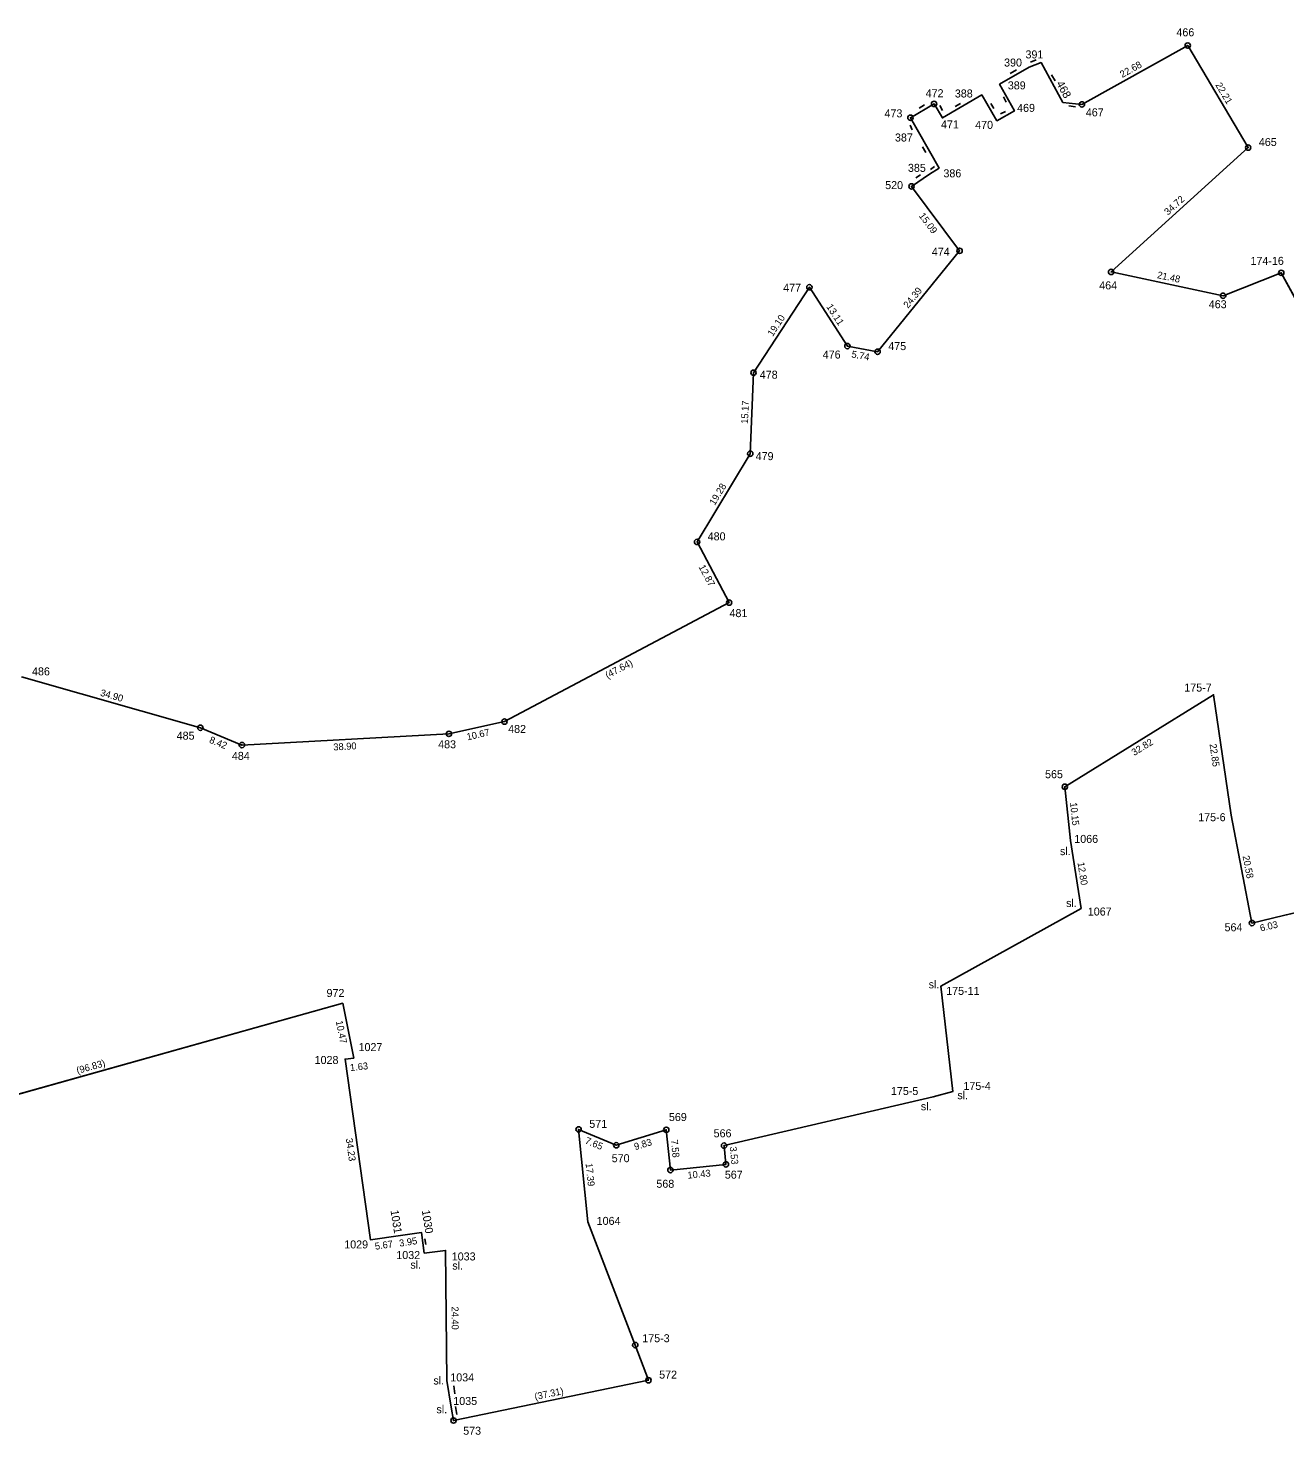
# Model space of a CAD drawing. Extents: x -555170 to -550532, y -1039598 to -1034701.
# Drawn here: x -554262.1 to -554026.5, y -1037853.4 to -1037589.8 of the extents above; entities that cross this region are included whole.
import ezdxf

# ---------------------------------------------------------------- set-up
doc = ezdxf.new("R2010")
doc.units = 0
for name, color, linetype in [('Vrstva 10', 7, 'Continuous'), ('Vrstva 40', 7, 'Continuous'), ('Vrstva 43', 7, 'Continuous'), ('Vrstva 48', 7, 'Continuous')]:
    doc.layers.add(name, color=color, linetype=linetype)

msp = doc.modelspace()

# ---------------------------------------------------------------- linework, layer by layer
at = {"layer": 'Vrstva 10'}
for p, q in [((-554073.13, -1037595.73), (-554074.17, -1037596.11)), ((-554076.83, -1037597.6), (-554077.99, -1037598.24)), ((-554070.26, -1037598.54), (-554069.58, -1037599.63)), ((-554079.26, -1037602.63), (-554078.76, -1037603.64)), ((-554094.09, -1037604.15), (-554095.08, -1037604.76)), ((-554091.18, -1037604.28), (-554090.67, -1037605.19)), ((-554087.3, -1037603.87), (-554088.34, -1037604.48)), ((-554081.62, -1037603.87), (-554081.09, -1037604.84)), ((-554078.91, -1037605.39), (-554079.8, -1037605.85)), ((-554065.78, -1037604.53), (-554066.99, -1037604.35)), ((-554096.78, -1037607.94), (-554096.35, -1037608.82)), ((-554094.45, -1037612.02), (-554093.84, -1037613.06)), ((-554092.22, -1037615.67), (-554092.95, -1037616.23)), ((-554094.83, -1037617.27), (-554095.72, -1037617.85)), ((-554187.7, -1037816.67), (-554187.55, -1037817.74)), ((-554182.31, -1037844.21), (-554182.1, -1037845.71)), ((-554181.94, -1037848.1), (-554181.69, -1037849.59))]:
    msp.add_line(p, q, dxfattribs=at)
at = {"layer": 'Vrstva 40'}
for p, q in [((-554044.74, -1037593.02), (-554064.56, -1037604.06)), ((-554033.4, -1037612.15), (-554044.74, -1037593.02)), ((-554074.45, -1037597.07), (-554080.01, -1037600.29)), ((-554072.22, -1037596.22), (-554074.45, -1037597.07)), ((-554068.14, -1037603.67), (-554072.22, -1037596.22)), ((-554080.01, -1037600.29), (-554077.21, -1037605.29)), ((-554083.34, -1037602.28), (-554090.72, -1037606.6)), ((-554080.48, -1037607.11), (-554083.34, -1037602.28)), ((-554064.56, -1037604.06), (-554068.14, -1037603.67)), ((-554092.27, -1037603.96), (-554096.7, -1037606.56)), ((-554090.72, -1037606.6), (-554092.27, -1037603.96)), ((-554077.21, -1037605.29), (-554080.48, -1037607.11)), ((-554096.7, -1037606.56), (-554095.19, -1037609.22)), ((-554095.19, -1037609.22), (-554091.35, -1037615.99)), ((-554059.09, -1037635.45), (-554033.4, -1037612.15)), ((-554091.35, -1037615.99), (-554093.16, -1037617.16)), ((-554093.16, -1037617.16), (-554096.5, -1037619.43)), ((-554096.5, -1037619.43), (-554087.48, -1037631.5)), ((-554087.48, -1037631.5), (-554102.86, -1037650.41)), ((-554038.11, -1037639.91), (-554059.09, -1037635.45)), ((-554027.21, -1037635.62), (-554038.11, -1037639.91)), ((-554013.33, -1037660.96), (-554027.21, -1037635.62)), ((-554115.65, -1037638.34), (-554126.11, -1037654.35)), ((-554108.53, -1037649.35), (-554115.65, -1037638.34)), ((-554102.86, -1037650.41), (-554108.53, -1037649.35)), ((-554126.11, -1037654.35), (-554126.72, -1037669.52)), ((-554126.72, -1037669.52), (-554136.7, -1037686.06)), ((-554136.7, -1037686.06), (-554130.68, -1037697.43)), ((-554130.68, -1037697.43), (-554172.78, -1037719.73)), ((-554229.79, -1037720.89), (-554263.34, -1037711.37)), ((-554067.76, -1037731.95), (-554039.89, -1037714.69)), ((-554039.89, -1037714.69), (-554036.61, -1037737.29)), ((-554221.99, -1037724.12), (-554229.79, -1037720.89)), ((-554183.2, -1037722.03), (-554221.99, -1037724.12)), ((-554172.78, -1037719.73), (-554183.2, -1037722.03)), ((-554066.7, -1037742.04), (-554067.76, -1037731.95)), ((-554036.61, -1037737.29), (-554032.69, -1037757.49)), ((-554064.72, -1037754.73), (-554066.7, -1037742.04)), ((-554026.81, -1037756.1), (-554004.57, -1037750.84)), ((-554090.99, -1037769.3), (-554064.72, -1037754.73)), ((-554032.69, -1037757.49), (-554026.81, -1037756.1)), ((-554088.77, -1037789.06), (-554090.99, -1037769.3)), ((-554296.34, -1037798.66), (-554203.1, -1037772.53)), ((-554203.1, -1037772.53), (-554201.05, -1037782.8)), ((-554201.05, -1037782.8), (-554202.66, -1037782.97)), ((-554202.66, -1037782.97), (-554197.89, -1037816.89)), ((-554131.64, -1037799.21), (-554092.45, -1037790.08)), ((-554092.45, -1037790.08), (-554088.77, -1037789.06)), ((-554157.14, -1037813.46), (-554158.89, -1037796.17)), ((-554158.89, -1037796.17), (-554151.83, -1037799.13)), ((-554151.83, -1037799.13), (-554142.46, -1037796.24)), ((-554142.46, -1037796.24), (-554141.69, -1037803.78)), ((-554131.28, -1037802.72), (-554131.64, -1037799.21)), ((-554141.69, -1037803.78), (-554131.28, -1037802.72)), ((-554148.27, -1037836.57), (-554157.14, -1037813.46)), ((-554197.89, -1037816.89), (-554192.28, -1037816.06)), ((-554188.36, -1037815.47), (-554192.28, -1037816.06)), ((-554188.36, -1037815.47), (-554187.83, -1037819.35)), ((-554187.83, -1037819.35), (-554183.83, -1037818.84)), ((-554183.83, -1037818.84), (-554183.61, -1037843.21)), ((-554145.8, -1037843.17), (-554148.27, -1037836.57)), ((-554183.61, -1037843.21), (-554182.77, -1037848.25)), ((-554182.34, -1037850.72), (-554145.8, -1037843.17)), ((-554182.77, -1037848.25), (-554182.34, -1037850.72))]:
    msp.add_line(p, q, dxfattribs=at)
at = {"layer": 'Vrstva 43'}
for p, q in [((-554044.74, -1037593.02), (-554044.74, -1037593.02)), ((-554074.45, -1037597.07), (-554074.45, -1037597.07)), ((-554072.22, -1037596.22), (-554072.22, -1037596.22)), ((-554080.01, -1037600.29), (-554080.01, -1037600.29)), ((-554083.34, -1037602.28), (-554083.34, -1037602.28)), ((-554068.14, -1037603.67), (-554068.14, -1037603.67)), ((-554092.27, -1037603.96), (-554092.27, -1037603.96)), ((-554077.21, -1037605.29), (-554077.21, -1037605.29)), ((-554064.56, -1037604.06), (-554064.56, -1037604.06)), ((-554096.7, -1037606.56), (-554096.7, -1037606.56)), ((-554090.72, -1037606.6), (-554090.72, -1037606.6)), ((-554080.48, -1037607.11), (-554080.48, -1037607.11)), ((-554095.19, -1037609.22), (-554095.19, -1037609.22)), ((-554033.4, -1037612.15), (-554033.4, -1037612.15)), ((-554091.35, -1037615.99), (-554091.35, -1037615.99)), ((-554096.5, -1037619.43), (-554096.5, -1037619.43)), ((-554093.16, -1037617.16), (-554093.16, -1037617.16)), ((-554087.48, -1037631.5), (-554087.48, -1037631.5)), ((-554059.09, -1037635.45), (-554059.09, -1037635.45)), ((-554027.21, -1037635.62), (-554027.21, -1037635.62)), ((-554115.65, -1037638.34), (-554115.65, -1037638.34)), ((-554038.11, -1037639.91), (-554038.11, -1037639.91)), ((-554108.53, -1037649.35), (-554108.53, -1037649.35)), ((-554102.86, -1037650.41), (-554102.86, -1037650.41)), ((-554126.11, -1037654.35), (-554126.11, -1037654.35)), ((-554126.72, -1037669.52), (-554126.72, -1037669.52)), ((-554136.7, -1037686.06), (-554136.7, -1037686.06)), ((-554130.68, -1037697.43), (-554130.68, -1037697.43)), ((-554039.89, -1037714.69), (-554039.89, -1037714.69)), ((-554229.79, -1037720.89), (-554229.79, -1037720.89)), ((-554183.2, -1037722.03), (-554183.2, -1037722.03)), ((-554172.78, -1037719.73), (-554172.78, -1037719.73)), ((-554221.99, -1037724.12), (-554221.99, -1037724.12)), ((-554067.76, -1037731.95), (-554067.76, -1037731.95)), ((-554036.61, -1037737.29), (-554036.61, -1037737.29)), ((-554066.7, -1037742.04), (-554066.7, -1037742.04)), ((-554064.72, -1037754.73), (-554064.72, -1037754.73)), ((-554026.81, -1037756.1), (-554026.81, -1037756.1)), ((-554032.69, -1037757.49), (-554032.69, -1037757.49)), ((-554090.99, -1037769.3), (-554090.99, -1037769.3)), ((-554203.1, -1037772.53), (-554203.1, -1037772.53)), ((-554202.66, -1037782.97), (-554202.66, -1037782.97)), ((-554201.05, -1037782.8), (-554201.05, -1037782.8)), ((-554092.45, -1037790.08), (-554092.45, -1037790.08)), ((-554088.77, -1037789.06), (-554088.77, -1037789.06)), ((-554158.89, -1037796.17), (-554158.89, -1037796.17)), ((-554142.46, -1037796.24), (-554142.46, -1037796.24)), ((-554151.83, -1037799.13), (-554151.83, -1037799.13)), ((-554131.64, -1037799.21), (-554131.64, -1037799.21)), ((-554141.69, -1037803.78), (-554141.69, -1037803.78)), ((-554131.28, -1037802.72), (-554131.28, -1037802.72)), ((-554157.14, -1037813.46), (-554157.14, -1037813.46)), ((-554197.89, -1037816.89), (-554197.89, -1037816.89)), ((-554192.28, -1037816.06), (-554192.28, -1037816.06)), ((-554188.36, -1037815.47), (-554188.36, -1037815.47)), ((-554187.83, -1037819.35), (-554187.83, -1037819.35)), ((-554183.83, -1037818.84), (-554183.83, -1037818.84)), ((-554148.27, -1037836.57), (-554148.27, -1037836.57)), ((-554183.61, -1037843.21), (-554183.61, -1037843.21)), ((-554145.8, -1037843.17), (-554145.8, -1037843.17)), ((-554182.77, -1037848.25), (-554182.77, -1037848.25)), ((-554182.34, -1037850.72), (-554182.34, -1037850.72))]:
    msp.add_line(p, q, dxfattribs=at)
for centre, radius in [((-554044.74, -1037593.02), 0.5), ((-554044.74, -1037593.02), 0.01), ((-554092.27, -1037603.96), 0.5), ((-554064.56, -1037604.06), 0.5), ((-554096.7, -1037606.56), 0.5), ((-554092.27, -1037603.96), 0.01), ((-554064.56, -1037604.06), 0.01), ((-554096.7, -1037606.56), 0.01), ((-554033.4, -1037612.15), 0.5), ((-554033.4, -1037612.15), 0.01), ((-554096.5, -1037619.43), 0.5), ((-554096.5, -1037619.43), 0.01), ((-554087.48, -1037631.5), 0.5), ((-554087.48, -1037631.5), 0.01), ((-554059.09, -1037635.45), 0.5), ((-554027.21, -1037635.62), 0.5), ((-554115.65, -1037638.34), 0.5), ((-554059.09, -1037635.45), 0.01), ((-554027.21, -1037635.62), 0.01), ((-554115.65, -1037638.34), 0.01), ((-554038.11, -1037639.91), 0.5), ((-554038.11, -1037639.91), 0.01), ((-554108.53, -1037649.35), 0.5), ((-554108.53, -1037649.35), 0.01), ((-554102.86, -1037650.41), 0.5), ((-554102.86, -1037650.41), 0.01), ((-554126.11, -1037654.35), 0.5), ((-554126.11, -1037654.35), 0.01), ((-554126.73, -1037669.52), 0.5), ((-554126.73, -1037669.52), 0.01), ((-554136.7, -1037686.06), 0.5), ((-554136.7, -1037686.06), 0.01), ((-554130.68, -1037697.43), 0.5), ((-554130.68, -1037697.43), 0.01), ((-554172.78, -1037719.73), 0.5), ((-554229.79, -1037720.89), 0.5), ((-554229.79, -1037720.89), 0.01), ((-554183.2, -1037722.03), 0.5), ((-554183.2, -1037722.03), 0.01), ((-554172.78, -1037719.73), 0.01), ((-554221.99, -1037724.12), 0.5), ((-554221.99, -1037724.12), 0.01), ((-554067.76, -1037731.95), 0.5), ((-554067.76, -1037731.95), 0.01), ((-554032.69, -1037757.49), 0.5), ((-554032.69, -1037757.49), 0.01), ((-554158.89, -1037796.17), 0.5), ((-554158.89, -1037796.17), 0.01), ((-554142.46, -1037796.24), 0.5), ((-554151.83, -1037799.13), 0.5), ((-554142.46, -1037796.24), 0.01), ((-554131.64, -1037799.21), 0.5), ((-554151.83, -1037799.13), 0.01), ((-554131.64, -1037799.21), 0.01), ((-554141.69, -1037803.78), 0.5), ((-554141.69, -1037803.78), 0.01), ((-554131.28, -1037802.72), 0.5), ((-554131.28, -1037802.72), 0.01), ((-554148.27, -1037836.57), 0.5), ((-554148.27, -1037836.57), 0.01), ((-554145.8, -1037843.17), 0.5), ((-554145.8, -1037843.17), 0.01), ((-554182.34, -1037850.72), 0.5), ((-554182.34, -1037850.72), 0.01)]:
    msp.add_circle(centre, radius, dxfattribs=at)
at = {"layer": 'Vrstva 48'}
for points in [[(-554263.34, -1037711.37), (-554229.79, -1037720.89), (-554221.99, -1037724.12), (-554183.2, -1037722.03), (-554172.78, -1037719.73), (-554130.68, -1037697.43), (-554136.7, -1037686.06), (-554126.72, -1037669.52), (-554126.11, -1037654.35), (-554115.65, -1037638.34), (-554108.53, -1037649.35), (-554102.86, -1037650.41), (-554087.48, -1037631.5), (-554096.5, -1037619.43), (-554093.16, -1037617.16), (-554091.35, -1037615.99), (-554095.19, -1037609.22), (-554096.7, -1037606.56), (-554092.27, -1037603.96), (-554090.72, -1037606.6), (-554083.34, -1037602.28), (-554080.48, -1037607.11), (-554077.21, -1037605.29), (-554080.01, -1037600.29), (-554074.45, -1037597.07), (-554072.22, -1037596.22), (-554068.14, -1037603.67), (-554064.56, -1037604.06), (-554044.74, -1037593.02), (-554033.4, -1037612.15), (-554059.09, -1037635.45), (-554038.11, -1037639.91), (-554027.21, -1037635.62), (-554013.33, -1037660.96)], [(-554004.57, -1037750.84), (-554026.81, -1037756.1), (-554032.69, -1037757.49), (-554036.61, -1037737.29), (-554039.89, -1037714.69), (-554067.76, -1037731.95), (-554066.7, -1037742.04), (-554064.72, -1037754.73), (-554090.99, -1037769.3), (-554088.77, -1037789.06), (-554092.45, -1037790.08), (-554131.64, -1037799.21), (-554131.28, -1037802.72), (-554141.69, -1037803.78), (-554142.46, -1037796.24), (-554151.83, -1037799.13), (-554158.89, -1037796.17), (-554157.14, -1037813.46), (-554148.27, -1037836.57), (-554145.8, -1037843.17), (-554182.34, -1037850.72), (-554182.77, -1037848.25), (-554183.61, -1037843.21), (-554183.83, -1037818.84), (-554187.83, -1037819.35), (-554188.36, -1037815.47), (-554192.28, -1037816.06), (-554197.89, -1037816.89), (-554202.66, -1037782.97), (-554201.05, -1037782.8), (-554203.1, -1037772.53), (-554296.34, -1037798.66)]]:
    msp.add_lwpolyline(points, dxfattribs=at)

# ---------------------------------------------------------------- texts
at = {"layer": 'Vrstva 10'}
for s, rotation, p in [('22.68', 29.135, (-554057, -1037599.11)), ('22.21', 300.679, (-554039.6, -1037600.41)), ('34.72', 42.2103, (-554048.43, -1037624.91)), ('15.09', 306.7591, (-554095.19, -1037624.95)), ('21.48', 347.9952, (-554050.55, -1037636.6)), ('24.39', 50.8857, (-554097.15, -1037642.36)), ('13.11', 302.867, (-554112.52, -1037641.97)), ('19.10', 56.8307, (-554122.51, -1037647.65)), ('5.74', 349.4545, (-554107.83, -1037651.46)), ('15.17', 87.6785, (-554127.15, -1037663.94)), ('19.28', 58.894, (-554133.38, -1037679.3)), ('12.87', 297.8923, (-554136.44, -1037690.73)), ('(47.64)', 27.9037, (-554153.49, -1037711.72)), ('34.90', 344.1534, (-554248.65, -1037714.87)), ('10.67', 12.4768, (-554179.72, -1037723.26)), ('8.42', 337.5442, (-554228.24, -1037723.64)), ('38.90', 3.0777, (-554204.83, -1037725.15)), ('32.82', 31.7747, (-554054.77, -1037726.2)), ('22.85', 278.2578, (-554040.65, -1037723.96)), ('10.15', 275.9691, (-554066.79, -1037734.94)), ('20.58', 280.9958, (-554034.46, -1037744.96)), ('12.80', 278.8683, (-554065.4, -1037746.17)), ('6.03', 13.3066, (-554031.03, -1037759.1)), ('10.47', 281.2885, (-554204.41, -1037775.9)), ('(96.83)', 15.6541, (-554252.8, -1037785.78)), ('1.63', 6.0275, (-554201.67, -1037785.23)), ('34.23', 278.0047, (-554202.53, -1037797.89)), ('7.65', 337.2356, (-554157.8, -1037798.74)), ('9.83', 17.1112, (-554148.27, -1037800.07)), ('7.58', 275.8273, (-554141.61, -1037798.14)), ('3.53', 275.8273, (-554130.58, -1037799.43)), ('17.39', 275.7631, (-554157.59, -1037802.55)), ('10.43', 5.8273, (-554138.43, -1037805.41)), ('5.67', 8.4159, (-554196.98, -1037818.73)), ('3.95', 8.5594, (-554192.42, -1037818.15)), ('24.40', 270.5172, (-554182.71, -1037829.36)), ('(37.31)', 11.6723, (-554167.01, -1037846.89))]:
    msp.add_text(s, height=1.3, rotation=rotation, dxfattribs=at).set_placement(p)
at = {"layer": 'Vrstva 43'}
for s, p in [('466', (-554046.85, -1037591.29)), ('390', (-554079.15, -1037596.96)), ('391', (-554075.14, -1037595.44)), ('389', (-554078.45, -1037601.24)), ('472', (-554093.85, -1037602.71)), ('388', (-554088.38, -1037602.76)), ('473', (-554101.56, -1037606.48)), ('469', (-554076.71, -1037605.46)), ('467', (-554063.83, -1037606.29)), ('471', (-554090.98, -1037608.56)), ('470', (-554084.57, -1037608.64)), ('387', (-554099.6, -1037611.01)), ('465', (-554031.4, -1037611.85)), ('385', (-554097.17, -1037616.7)), ('386', (-554090.52, -1037617.72)), ('520', (-554101.44, -1037619.93)), ('474', (-554092.69, -1037632.41)), ('174-16', (-554032.97, -1037634.13)), ('477', (-554120.55, -1037639.16)), ('464', (-554061.32, -1037638.73)), ('463', (-554040.79, -1037642.26)), ('476', (-554113.14, -1037651.69)), ('475', (-554100.86, -1037650.11)), ('478', (-554124.94, -1037655.46)), ('479', (-554125.71, -1037670.73)), ('480', (-554134.7, -1037685.76)), ('481', (-554130.61, -1037700.15)), ('486', (-554261.34, -1037711.07)), ('175-7', (-554045.37, -1037714.11)), ('485', (-554234.23, -1037723.12)), ('482', (-554172.1, -1037721.86)), ('483', (-554185.22, -1037724.73)), ('484', (-554223.88, -1037726.91)), ('565', (-554071.47, -1037730.34)), ('175-6', (-554042.77, -1037738.4)), ('sl.', (-554068.68, -1037744.76)), ('1066', (-554065.99, -1037742.47)), ('sl.', (-554067.53, -1037754.49)), ('1067', (-554063.46, -1037756.08)), ('564', (-554037.83, -1037759.03)), ('sl.', (-554093.29, -1037769.73)), ('175-11', (-554090, -1037770.95)), ('972', (-554206.14, -1037771.35)), ('1027', (-554200.14, -1037781.48)), ('1028', (-554208.37, -1037783.9)), ('175-5', (-554100.36, -1037789.72)), ('175-4', (-554086.77, -1037788.76)), ('sl.', (-554087.91, -1037790.5)), ('569', (-554141.97, -1037794.59)), ('sl.', (-554094.75, -1037792.58)), ('571', (-554156.89, -1037795.87)), ('566', (-554133.59, -1037797.64)), ('570', (-554152.69, -1037802.31)), ('567', (-554131.49, -1037805.39)), ('568', (-554144.32, -1037807.1)), ('1064', (-554155.51, -1037814.06)), ('1029', (-554202.82, -1037818.47)), ('1032', (-554193.06, -1037820.46)), ('1033', (-554182.67, -1037820.72)), ('sl.', (-554190.43, -1037822.27)), ('sl.', (-554182.57, -1037822.44)), ('175-3', (-554146.96, -1037836.05)), ('sl.', (-554186.11, -1037843.97)), ('1034', (-554182.94, -1037843.39)), ('572', (-554143.8, -1037842.87)), ('sl.', (-554185.54, -1037849.36)), ('1035', (-554182.38, -1037847.81)), ('573', (-554180.53, -1037853.39))]:
    msp.add_text(s, height=1.5, dxfattribs=at).set_placement(p)
for s, rotation, p in [('468', 298.8, (-554069.42, -1037600.14)), ('1031', 279, (-554194.15, -1037811.36)), ('1030', 279, (-554188.29, -1037811.36))]:
    msp.add_text(s, height=1.5, rotation=rotation, dxfattribs=at).set_placement(p)

doc.saveas('drawing.dxf')
